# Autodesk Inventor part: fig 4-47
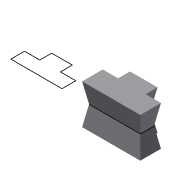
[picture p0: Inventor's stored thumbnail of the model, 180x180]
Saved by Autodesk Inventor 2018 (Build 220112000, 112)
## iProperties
Created: 2004-05
Part Number: fig 4-47
Document SubType Name: Modeling
Designer: CADCIM Technologies
Manufacturer: Standard
Standards Organization: Custom
Density: 1 g/cm^3
Material: Generic
Appearance: Default
Author: CADCIM Technologies
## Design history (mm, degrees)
sketch "Sketch1"
  geometry: L1 (31.783, 34.561)-(31.783, 22.933); L2 (31.783, 22.933)-(16.796, 22.933); L3 (16.796, 22.933)-(16.796, 9.496); L4 (16.796, 9.496)-(66.925, 9.496); L5 (66.925, 9.496)-(66.925, 22.933); L6 (66.925, 22.933)-(51.938, 22.933); L7 (51.938, 22.933)-(51.938, 34.561); L8 (51.938, 34.561)-(31.783, 34.561); L9 (-45.013, 34.561)-(-45.013, 22.933); L10 (-45.013, 22.933)-(-60, 22.933); L11 (-60, 22.933)-(-60, 9.496); L12 (-60, 9.496)-(-9.871, 9.496); L13 (-9.871, 9.496)-(-9.871, 22.933); L14 (-9.871, 22.933)-(-24.858, 22.933); L15 (-24.858, 22.933)-(-24.858, 34.561); L16 (-24.858, 34.561)-(-45.013, 34.561)
  constraints: 32 end point, 10 parallel, 4 equal length, 2 collinear, 2 perpendicular, 2 vertical
extrude "Extrusion2" new body sketch "Sketch1" stored distance "d2" = 38.75; taper "d3" = 10 deg
body "Solid2"
